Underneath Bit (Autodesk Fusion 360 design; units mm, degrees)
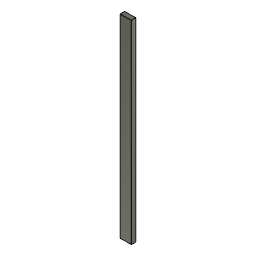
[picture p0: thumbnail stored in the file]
sketch "Sketch1" plane through (0, 0, 0) normal (0, 1, 0) x axis (1, 0, 0)
  line L1 (19.05, -1.3144) -> (0, -1.3144)
  line L2 (19.05, -331.5144) -> (19.05, -1.3144)
  line L3 (0, -331.5144) -> (19.05, -331.5144)
  line L4 (0, -1.3144) -> (0, -331.5144)
  point P2 (0, -1.3144)
  point P3 (19.05, -1.3144)
  point P5 (0, -331.5144)
  horizontal L1
  vertical L2
  horizontal L3
  vertical L4
  dimension "d1" distance P2 P3 = 19.05
  dimension "d2" distance P2 P5 = 330.2
extrude "Extrude1" new body sketch "Sketch1" along normal blind 7.9375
